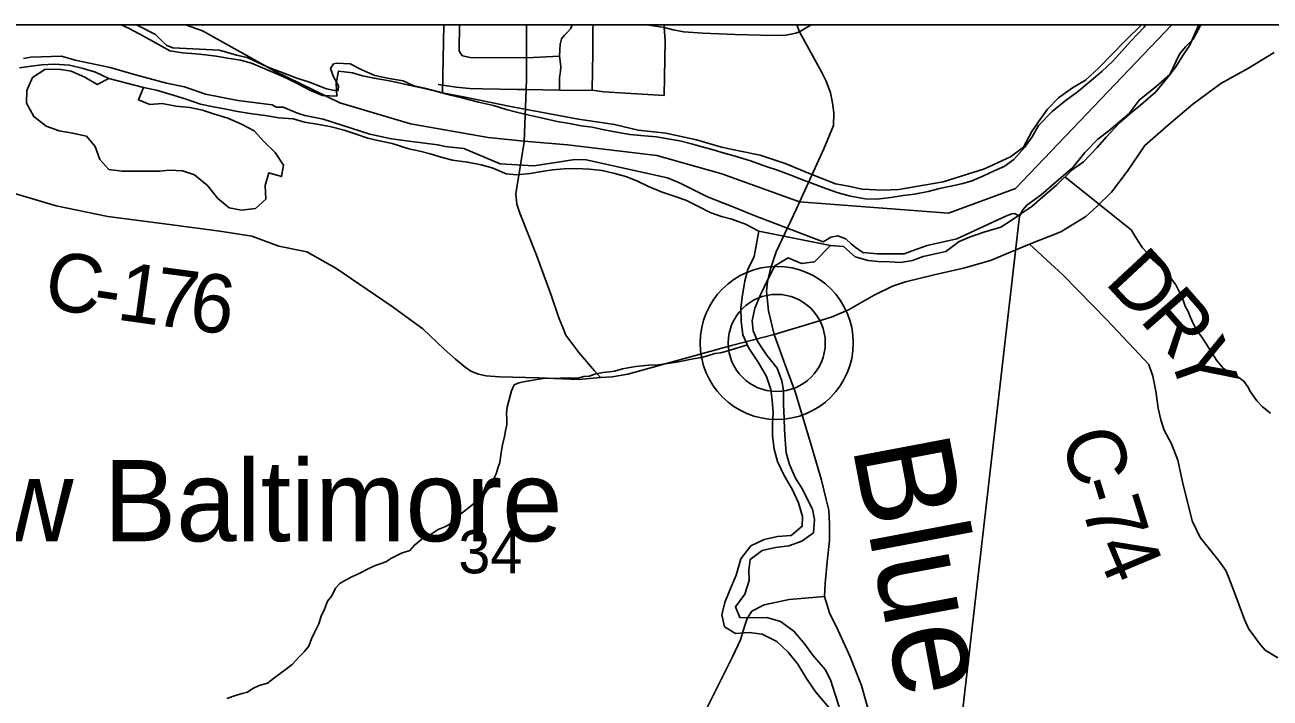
# Model space of a CAD drawing. Extents: x 0 to 34, y 0 to 22.
# Drawn here: x 5.755 to 6.965, y 20.246 to 20.9 of the extents above; entities that cross this region are included whole.
import ezdxf

# ---------------------------------------------------------------- set-up
doc = ezdxf.new("R2010")
doc.units = 0
for name, color, linetype in [('Default', 7, 'Continuous'), ('GM_X_County_Road', 7, 'Continuous'), ('GM_X_County_Road_Text', 7, 'Continuous'), ('GM_X_Major_River', 7, 'Continuous'), ('GM_X_Minor_River', 7, 'Continuous'), ('GM_X_Minor_River_Text', 7, 'Continuous'), ('GM_X_Section', 7, 'Continuous'), ('GM_X_Section_Text', 7, 'Continuous'), ('GM_X_State_Route', 7, 'Continuous'), ('GM_X_Township_Road', 7, 'Continuous'), ('GM_X_Unincorporated', 7, 'Continuous'), ('GM_X_Unincorporated_Location', 7, 'Continuous'), ('GM_X_Unincorporated_Text', 7, 'Continuous'), ('SH_Data', 7, 'Continuous')]:
    doc.layers.add(name, color=color, linetype=linetype)

msp = doc.modelspace()

# ---------------------------------------------------------------- linework, layer by layer
at = {"layer": 'Default'}
for points in [[(6.1618, 20.9), (5.8632, 20.9), (5.8814, 20.8906), (5.888, 20.8843), (5.8925, 20.8801), (5.8985, 20.8777), (5.9439, 20.8754), (5.9604, 20.8705), (5.9706, 20.8683), (5.9901, 20.8591), (6.0021, 20.8547), (6.019, 20.8482), (6.0303, 20.8445), (6.0479, 20.8377), (6.0555, 20.8363), (6.0592, 20.8363), (6.0593, 20.8408), (6.0546, 20.8496), (6.0518, 20.8576), (6.0546, 20.8621), (6.0576, 20.8628), (6.0709, 20.8621), (6.0821, 20.8562), (6.0948, 20.8509), (6.1088, 20.8479), (6.1224, 20.8457), (6.1328, 20.8409), (6.143, 20.8384), (6.1607, 20.8338)], [(6.8402, 20.9), (6.1618, 20.9), (6.1607, 20.8338), (6.1826, 20.8299), (6.2267, 20.8208), (6.2927, 20.8082), (6.3278, 20.8032), (6.3508, 20.7977), (6.3776, 20.7948), (6.4074, 20.7884), (6.4318, 20.781), (6.4503, 20.7772), (6.4695, 20.7733), (6.4936, 20.7651), (6.5179, 20.7551), (6.5427, 20.7454), (6.5552, 20.7432), (6.5687, 20.7402), (6.5888, 20.7393), (6.6043, 20.7401), (6.6473, 20.7474), (6.6874, 20.76), (6.7127, 20.7719), (6.7254, 20.7811), (6.7337, 20.7964), (6.7396, 20.8054), (6.7487, 20.818), (6.7595, 20.8291), (6.773, 20.8387), (6.7857, 20.8463), (6.7985, 20.8581), (6.8245, 20.8848)], [(7.4473, 20.9), (6.898, 20.9), (6.8905, 20.8862), (6.8831, 20.8788), (6.8772, 20.8714), (6.8677, 20.8519), (6.8545, 20.8401), (6.8379, 20.8269), (6.8281, 20.8138), (6.8084, 20.7969), (6.7976, 20.7888), (6.7851, 20.7759), (6.7734, 20.7614), (6.7572, 20.7474), (6.7425, 20.7348), (6.7286, 20.7246), (6.7247, 20.7201), (6.7215, 20.7141), (6.6475, 20.0689), (7.4124, 20.0219)]]:
    msp.add_lwpolyline(points, close=True, dxfattribs=at)
at = {"layer": 'GM_X_County_Road'}
for p, q in [((6.5051, 20.9), (6.5076, 20.8933)), ((6.5076, 20.8933), (6.5191, 20.9))]:
    msp.add_line(p, q, dxfattribs=at)
for points in [[(6.2421, 20.8476), (6.2423, 20.8681), (6.2422, 20.9)], [(6.3593, 20.9), (6.376, 20.8975), (6.3847, 20.8952), (6.3952, 20.8932), (6.4138, 20.8919), (6.445, 20.8906), (6.482, 20.8898), (6.4945, 20.8899), (6.5042, 20.8921), (6.5076, 20.8933)], [(6.5076, 20.8933), (6.5295, 20.8536), (6.5335, 20.8453), (6.5378, 20.834), (6.5397, 20.8242), (6.5411, 20.8145), (6.5406, 20.8022), (6.5313, 20.7796), (6.5077, 20.7276), (6.5048, 20.7213)], [(6.483, 20.5991), (6.5239, 20.6114), (6.5394, 20.6162), (6.5552, 20.6229), (6.5802, 20.6371), (6.5982, 20.6461), (6.6106, 20.6501), (6.6385, 20.657), (6.667, 20.6634), (6.6933, 20.6708), (6.7314, 20.6867), (6.7616, 20.6989), (6.7859, 20.7138), (6.7968, 20.7233), (6.8109, 20.7374), (6.8263, 20.7575), (6.8434, 20.7828), (6.8667, 20.8031), (6.8901, 20.8229), (6.9172, 20.8431), (6.9443, 20.8579), (6.969, 20.8732)], [(6.2401, 20.7864), (6.242, 20.8373), (6.2421, 20.8476)], [(6.2768, 20.6074), (6.2736, 20.6153), (6.2661, 20.6374), (6.2518, 20.6763), (6.2358, 20.717), (6.2327, 20.7256), (6.232, 20.7359), (6.2401, 20.7864)], [(5.7288, 20.7406), (5.785, 20.7242), (5.8352, 20.7136), (5.895, 20.7059), (5.9442, 20.6995), (5.9752, 20.6945), (6.0015, 20.685), (6.0287, 20.6793), (6.0569, 20.6634), (6.1106, 20.627), (6.1415, 20.6045), (6.1622, 20.5846), (6.1731, 20.5749), (6.1826, 20.5672), (6.1881, 20.5633), (6.1956, 20.5605), (6.203, 20.5588), (6.216, 20.5577), (6.2538, 20.5568), (6.2928, 20.5554), (6.3142, 20.5572)], [(6.5048, 20.7213), (6.4851, 20.6794), (6.4796, 20.6627), (6.4764, 20.6503), (6.4756, 20.6413), (6.4775, 20.6219), (6.483, 20.5991)], [(6.7314, 20.6867), (6.7638, 20.657), (6.8065, 20.6133), (6.8329, 20.5852), (6.8472, 20.5698), (6.8511, 20.5585), (6.8542, 20.544), (6.8565, 20.5275), (6.859, 20.5162), (6.8623, 20.506), (6.8692, 20.4928), (6.8756, 20.4768), (6.8808, 20.4529), (6.8841, 20.4389), (6.8893, 20.418), (6.8973, 20.4016), (6.9067, 20.3901), (6.9156, 20.3785), (6.922, 20.3695), (6.925, 20.3625), (6.9299, 20.3497), (6.9402, 20.3219), (6.9445, 20.3127), (6.9497, 20.3057), (6.9546, 20.2989), (6.9603, 20.292), (6.9727, 20.2847)], [(6.3142, 20.5572), (6.3083, 20.5636), (6.293, 20.5814), (6.2805, 20.5985), (6.2768, 20.6074)], [(6.3142, 20.5572), (6.3255, 20.5578), (6.3406, 20.5603), (6.4416, 20.5884), (6.483, 20.5991)], [(6.483, 20.5991), (6.4951, 20.5661), (6.5033, 20.5433), (6.5176, 20.4961), (6.5292, 20.4573), (6.5335, 20.4387), (6.5361, 20.4282), (6.5369, 20.4149), (6.5367, 20.3986), (6.5344, 20.3779), (6.5325, 20.3569), (6.5319, 20.3443), (6.5369, 20.3283), (6.5453, 20.3111), (6.5569, 20.2857), (6.5678, 20.2579), (6.5768, 20.2264)], [(6.4543, 20.315), (6.4569, 20.3229), (6.4612, 20.33), (6.4732, 20.3361), (6.4977, 20.3413), (6.5319, 20.3443)], [(6.4159, 20.2324), (6.4425, 20.2857), (6.4502, 20.3022), (6.4543, 20.315)]]:
    msp.add_lwpolyline(points, dxfattribs=at)
at = {"layer": 'GM_X_Major_River'}
for p, q in [((5.8363, 20.848), (5.8699, 20.8392)), ((6.4682, 20.6995), (6.5378, 20.6854))]:
    msp.add_line(p, q, dxfattribs=at)
for points in [[(6.8441, 20.9), (6.8426, 20.8979), (6.8301, 20.8845), (6.8211, 20.8744), (6.8122, 20.8647), (6.8017, 20.8547), (6.7916, 20.8462), (6.7793, 20.8358), (6.7657, 20.8259), (6.7534, 20.8159), (6.7401, 20.8021), (6.7338, 20.7912), (6.7264, 20.7807), (6.7162, 20.7692), (6.7066, 20.7622), (6.697, 20.7582), (6.6859, 20.7528), (6.6747, 20.7481), (6.6652, 20.7456), (6.6549, 20.7432), (6.6438, 20.7408), (6.6327, 20.738), (6.6194, 20.7356), (6.6083, 20.734), (6.5965, 20.7323), (6.5828, 20.7307), (6.5714, 20.731), (6.5571, 20.7336), (6.5454, 20.7369), (6.5333, 20.741), (6.5228, 20.745), (6.5115, 20.7491), (6.4991, 20.7539), (6.4863, 20.7588), (6.4753, 20.7625), (6.4599, 20.7677), (6.4452, 20.7723), (6.4335, 20.7756), (6.4237, 20.7785), (6.4131, 20.7814), (6.4014, 20.7847), (6.3912, 20.7872), (6.3795, 20.7893), (6.3685, 20.7911), (6.3571, 20.7921), (6.3427, 20.7936), (6.3299, 20.7958), (6.3178, 20.798), (6.3061, 20.8005), (6.2955, 20.8019), (6.2841, 20.804), (6.272, 20.8062), (6.2565, 20.8096), (6.2448, 20.8121), (6.2324, 20.8151), (6.2225, 20.8176), (6.2101, 20.8217), (6.1957, 20.825), (6.1795, 20.8292), (6.1682, 20.8317), (6.1538, 20.8355), (6.1402, 20.8388), (6.1278, 20.8414), (6.1168, 20.8439), (6.107, 20.8461), (6.0941, 20.8482), (6.0828, 20.8504), (6.073, 20.8533), (6.0593, 20.8551), (6.0572, 20.8434), (6.0577, 20.8308), (6.044, 20.8315), (6.0316, 20.8367), (6.0207, 20.8423), (6.0094, 20.8479), (5.9985, 20.8527), (5.9857, 20.8583), (5.9748, 20.8627), (5.9643, 20.8656), (5.9514, 20.8678), (5.9404, 20.8696), (5.9302, 20.8709), (5.9207, 20.8719), (5.9079, 20.873), (5.8954, 20.8748), (5.8822, 20.8823), (5.8699, 20.889), (5.856, 20.8966), (5.8482, 20.9)], [(6.5378, 20.6854), (6.5506, 20.6847), (6.5618, 20.6746), (6.5743, 20.6709), (6.5841, 20.6699), (6.5955, 20.6696), (6.6057, 20.669), (6.6175, 20.671), (6.6279, 20.675), (6.6382, 20.677), (6.65, 20.6798), (6.6628, 20.6894), (6.6731, 20.6937), (6.6869, 20.6984), (6.7033, 20.7033), (6.7134, 20.7099), (6.7238, 20.7169), (6.7334, 20.7235), (6.7443, 20.7328), (6.7574, 20.7443), (6.7726, 20.7592), (6.7838, 20.7669), (6.797, 20.7807), (6.8059, 20.7907), (6.8188, 20.8049), (6.8289, 20.8134), (6.8393, 20.8219), (6.854, 20.8349), (6.8657, 20.8491), (6.8736, 20.8592), (6.8803, 20.8704), (6.887, 20.8802), (6.8926, 20.893), (6.896, 20.9)], [(5.7492, 20.8583), (5.7606, 20.8599), (5.7709, 20.8612), (5.7834, 20.8617), (5.7978, 20.861), (5.8111, 20.8577), (5.8231, 20.854), (5.8363, 20.848)], [(5.8699, 20.8392), (5.8824, 20.8367), (5.8955, 20.8326), (5.9103, 20.828), (5.9253, 20.8231), (5.9378, 20.8202), (5.9503, 20.818), (5.9612, 20.8159), (5.9756, 20.8136), (5.9881, 20.8118), (6.0014, 20.8096), (6.0154, 20.8086), (6.0263, 20.8053), (6.0384, 20.8035), (6.0509, 20.8013), (6.0649, 20.7976), (6.0747, 20.7943), (6.0879, 20.7898), (6.0977, 20.7877), (6.1117, 20.7847), (6.1279, 20.7794), (6.1385, 20.7773), (6.1487, 20.7748), (6.1592, 20.7715), (6.1702, 20.7686), (6.1849, 20.7667), (6.1982, 20.7641), (6.2087, 20.7612), (6.2226, 20.7552), (6.2325, 20.7542), (6.2458, 20.7555), (6.2572, 20.7575), (6.2675, 20.7592), (6.2789, 20.76), (6.2907, 20.7605), (6.3036, 20.7599), (6.3157, 20.7585), (6.3282, 20.7555), (6.3399, 20.7522), (6.3501, 20.7482), (6.361, 20.743), (6.3741, 20.7374), (6.3869, 20.7333), (6.3971, 20.7296), (6.4095, 20.7236), (6.4208, 20.7177), (6.4317, 20.7136), (6.4419, 20.7111), (6.4551, 20.7063), (6.4682, 20.6995)]]:
    msp.add_lwpolyline(points, dxfattribs=at)
at = {"layer": 'GM_X_Minor_River'}
for p, q in [((5.8699, 20.8392), (5.8363, 20.848)), ((6.5378, 20.6854), (6.4682, 20.6995))]:
    msp.add_line(p, q, dxfattribs=at)
for points in [[(5.8363, 20.848), (5.8248, 20.8421), (5.8128, 20.8492), (5.7996, 20.8549), (5.7875, 20.857), (5.7738, 20.8566), (5.7619, 20.8489), (5.7563, 20.8361), (5.756, 20.8239), (5.7633, 20.8108), (5.7752, 20.8014), (5.788, 20.7969), (5.8009, 20.7948), (5.8145, 20.7918), (5.823, 20.7817), (5.8273, 20.7691), (5.8362, 20.7594), (5.8491, 20.7579), (5.8616, 20.7577), (5.876, 20.7577), (5.8855, 20.7579), (5.895, 20.7588), (5.9079, 20.7581), (5.9196, 20.7541), (5.9323, 20.7435), (5.9419, 20.7315), (5.953, 20.7221), (5.9651, 20.72), (5.9789, 20.7216), (5.9889, 20.7305), (5.9881, 20.7438), (5.9918, 20.7562), (6.0042, 20.7525), (6.006, 20.7635), (5.9979, 20.7759), (5.9872, 20.7864), (5.9775, 20.7969), (5.9651, 20.8036), (5.952, 20.8092), (5.938, 20.8137), (5.9271, 20.817), (5.915, 20.8196), (5.9014, 20.821), (5.8881, 20.8236), (5.876, 20.8227), (5.865, 20.8272), (5.8699, 20.8392)], [(6.7655, 20.7523), (6.8302, 20.7007), (6.8336, 20.6949), (6.8369, 20.6899), (6.8413, 20.6833), (6.8462, 20.6776), (6.8507, 20.6722), (6.8611, 20.6628), (6.8664, 20.657), (6.8697, 20.6524), (6.8734, 20.6474), (6.8764, 20.6416), (6.8793, 20.6363), (6.8826, 20.6267), (6.8855, 20.6213), (6.8877, 20.6155), (6.891, 20.6083), (6.8947, 20.6021), (6.8988, 20.5963), (6.9021, 20.5917), (6.9054, 20.5863), (6.9099, 20.5794), (6.9132, 20.574), (6.9195, 20.5663), (6.9274, 20.5608), (6.9338, 20.5577), (6.9395, 20.5538), (6.9436, 20.548), (6.9461, 20.5434), (6.9524, 20.5345), (6.9577, 20.5287), (6.9656, 20.5225)], [(6.4682, 20.6995), (6.4635, 20.6749), (6.4575, 20.6621), (6.4546, 20.6511), (6.4519, 20.6352), (6.4506, 20.6246), (6.451, 20.612), (6.4526, 20.5987), (6.4584, 20.5856), (6.4676, 20.5721), (6.4756, 20.5583), (6.4799, 20.5456), (6.4812, 20.5353), (6.482, 20.5227), (6.4814, 20.5129), (6.4815, 20.5007), (6.4831, 20.4874), (6.4863, 20.4755), (6.4928, 20.462), (6.5005, 20.4486), (6.5067, 20.4355), (6.5105, 20.4221), (6.5103, 20.4126), (6.4995, 20.4037), (6.4862, 20.4025), (6.4732, 20.3997), (6.4605, 20.3936), (6.4507, 20.3809), (6.4462, 20.365), (6.4406, 20.3522), (6.435, 20.3386), (6.432, 20.3265), (6.4348, 20.3147), (6.4453, 20.3084), (6.4586, 20.3092), (6.4715, 20.3078), (6.4857, 20.3006), (6.4965, 20.2901), (6.5061, 20.2785), (6.5145, 20.2646), (6.5237, 20.2514), (6.5474, 20.2232)], [(6.5462, 20.2369), (6.5423, 20.2491), (6.5377, 20.2633), (6.5326, 20.2733), (6.5204, 20.2876), (6.5127, 20.2981), (6.5023, 20.3105), (6.4892, 20.3199), (6.476, 20.324), (6.4627, 20.3236), (6.4498, 20.3238), (6.4455, 20.3342), (6.4545, 20.3466), (6.4586, 20.3598), (6.4585, 20.37), (6.4598, 20.3803), (6.4714, 20.3891), (6.4844, 20.3919), (6.4973, 20.3935), (6.51, 20.3982), (6.5212, 20.4063), (6.5222, 20.4192), (6.5202, 20.4291), (6.5155, 20.4387), (6.5107, 20.4487), (6.5038, 20.4595), (6.498, 20.4726), (6.4948, 20.4841), (6.4936, 20.4966), (6.4931, 20.5065), (6.4926, 20.5172), (6.4921, 20.5309), (6.492, 20.5446), (6.4904, 20.5541), (6.4861, 20.5664), (6.4757, 20.5792), (6.4673, 20.5919), (6.4626, 20.6027), (6.4617, 20.6122), (6.4642, 20.6247), (6.4698, 20.6375), (6.477, 20.6525), (6.4838, 20.6657), (6.4965, 20.6734), (6.5096, 20.6681), (6.5222, 20.6698), (6.5378, 20.6854)], [(6.457, 20.5889), (6.4371, 20.5829), (6.431, 20.5811), (6.4253, 20.5804), (6.4172, 20.5779), (6.4123, 20.5768), (6.4043, 20.5754), (6.3901, 20.5726), (6.3794, 20.5709), (6.3703, 20.5695), (6.3611, 20.5693), (6.3546, 20.5686), (6.3485, 20.5679), (6.3428, 20.5669), (6.3356, 20.5655), (6.3279, 20.5633), (6.3229, 20.5626), (6.3165, 20.562), (6.3096, 20.5609), (6.3031, 20.5584), (6.2981, 20.5581), (6.2931, 20.557), (6.2886, 20.5567), (6.2836, 20.5568), (6.2749, 20.5566), (6.2688, 20.5563), (6.2638, 20.5564), (6.2585, 20.5561), (6.2524, 20.5554), (6.2447, 20.554), (6.2394, 20.5529), (6.2348, 20.5519), (6.2302, 20.55), (6.2278, 20.5444), (6.225, 20.5345), (6.2233, 20.5284), (6.2228, 20.5224), (6.2231, 20.5159), (6.223, 20.5113), (6.2218, 20.5052), (6.2209, 20.4999), (6.2189, 20.4919), (6.2176, 20.4843), (6.2163, 20.4745), (6.2143, 20.4692), (6.2126, 20.4635), (6.2095, 20.457), (6.2063, 20.451), (6.202, 20.4446), (6.1962, 20.439), (6.1892, 20.433), (6.1838, 20.4289), (6.1769, 20.4233), (6.1722, 20.4177), (6.1676, 20.4147), (6.163, 20.4121), (6.1565, 20.4095), (6.1476, 20.4036), (6.1422, 20.4014), (6.1333, 20.3943), (6.1287, 20.389), (6.1206, 20.3865), (6.111, 20.3817), (6.1056, 20.378), (6.101, 20.3765), (6.0961, 20.3747), (6.0903, 20.3721), (6.0788, 20.3662), (6.073, 20.3636), (6.0661, 20.3603), (6.0607, 20.357), (6.0564, 20.3525), (6.0529, 20.3449), (6.0486, 20.3397), (6.0458, 20.3321), (6.0426, 20.3253), (6.0402, 20.3177), (6.0366, 20.3098), (6.0331, 20.303), (6.0307, 20.2961), (6.026, 20.2905), (6.0213, 20.2856), (6.0144, 20.2781), (6.009, 20.274), (6.0016, 20.2684), (5.9962, 20.2647), (5.9904, 20.2602), (5.9824, 20.2577), (5.9762, 20.2547), (5.9709, 20.2514), (5.9659, 20.25), (5.9594, 20.2482), (5.9509, 20.2452)]]:
    msp.add_lwpolyline(points, dxfattribs=at)
at = {"layer": 'GM_X_Section'}
msp.add_lwpolyline([(5.7531, 20.8675), (5.7604, 20.8685), (5.7903, 20.8697), (5.8035, 20.8656), (5.8374, 20.8587), (5.8622, 20.8516), (5.8923, 20.8433), (5.9097, 20.8399), (5.9303, 20.8326), (5.9616, 20.8265), (5.9949, 20.8223), (5.999, 20.8199), (6.0058, 20.8201), (6.0197, 20.8141), (6.0268, 20.812), (6.0445, 20.8082), (6.09, 20.7938), (6.1111, 20.7892), (6.133, 20.7864), (6.1561, 20.7835), (6.1632, 20.7818), (6.1814, 20.7799), (6.2166, 20.765), (6.2495, 20.7631), (6.2686, 20.766), (6.2891, 20.7693), (6.3001, 20.7687), (6.3426, 20.7593), (6.3792, 20.7512), (6.3916, 20.746), (6.4181, 20.7329), (6.4437, 20.7228), (6.4635, 20.7147), (6.5307, 20.6892), (6.5346, 20.6914), (6.538, 20.6936), (6.5449, 20.6949), (6.5528, 20.6921), (6.558, 20.687), (6.5617, 20.6839), (6.5691, 20.6788), (6.5835, 20.6773), (6.6093, 20.6775), (6.6173, 20.6803), (6.6318, 20.6856), (6.6607, 20.6921), (6.709, 20.7144), (6.714, 20.7162), (6.7167, 20.7165), (6.7215, 20.7141), (6.6475, 20.0689)], dxfattribs=at)
at = {"layer": 'GM_X_State_Route'}
msp.add_lwpolyline([(8.9, 16.8616), (8.9, 20.9), (6.8697, 20.9), (6.7177, 20.7411), (6.6525, 20.7169), (6.5075, 20.7281), (6.4321, 20.7553), (6.3691, 20.7729), (6.282, 20.7835), (6.2399, 20.787), (6.2051, 20.7905), (6.1295, 20.8038), (6.0609, 20.8242), (5.9975, 20.8551), (5.9272, 20.8941), (5.9107, 20.9), (5.6847, 20.9)], dxfattribs=at)
msp.add_lwpolyline([(6.8697, 20.9), (5.9107, 20.9), (5.9272, 20.8941), (5.9975, 20.8551), (6.0609, 20.8242), (6.1295, 20.8038), (6.2051, 20.7905), (6.2399, 20.787), (6.282, 20.7835), (6.3691, 20.7729), (6.4321, 20.7553), (6.5075, 20.7281), (6.6525, 20.7169), (6.7177, 20.7411)], close=True, dxfattribs=at)
at = {"layer": 'GM_X_Township_Road'}
msp.add_line((6.1772, 20.9), (6.1767, 20.8751), dxfattribs=at)
for points in [[(6.2744, 20.8367), (6.2743, 20.8488), (6.2752, 20.8547), (6.2757, 20.8595), (6.2742, 20.8695), (6.2749, 20.8812), (6.2762, 20.8866), (6.2791, 20.8901), (6.2819, 20.8927), (6.2854, 20.8965), (6.2865, 20.9)], [(6.3072, 20.9), (6.3068, 20.8963), (6.3066, 20.8732), (6.3061, 20.8365)], [(6.3761, 20.9), (6.376, 20.8975), (6.3771, 20.8848), (6.376, 20.8314)], [(6.1767, 20.8751), (6.178, 20.8723), (6.18, 20.87), (6.1874, 20.8684), (6.2423, 20.8681), (6.2742, 20.8695)], [(6.1993, 20.8379), (6.1867, 20.8381), (6.1739, 20.8395), (6.1565, 20.8421)], [(6.242, 20.8373), (6.2329, 20.8373), (6.1993, 20.8379)], [(6.376, 20.8314), (6.3174, 20.8348), (6.3061, 20.8365), (6.2951, 20.8363), (6.2744, 20.8367), (6.242, 20.8373)]]:
    msp.add_lwpolyline(points, dxfattribs=at)
at = {"layer": 'GM_X_Unincorporated'}
for radius in [0.0744, 0.0472]:
    msp.add_circle((6.4855, 20.5908), radius, dxfattribs=at)
at = {"layer": 'GM_X_Unincorporated_Location'}
msp.add_line((6.4855, 20.5908), (6.4855, 20.5908), dxfattribs=at)
at = {"layer": 'SH_Data'}
msp.add_line((2.1, 20.9), (8.9, 20.9), dxfattribs=at)

# ---------------------------------------------------------------- texts
at = {"layer": 'GM_X_County_Road_Text'}
for s, rotation, p in [('C', 349.3103, (5.7708, 20.6263)), ('D', 312.964, (6.8034, 20.6493)), ('1', 351.9682, (5.8426, 20.6137)), ('7', 352.3966, (5.8777, 20.6087)), ('6', 352.5029, (5.9125, 20.6041)), ('-', 351.4236, (5.819, 20.6173)), ('R', 311.2392, (6.8372, 20.6131)), ('Y', 289.7451, (6.8651, 20.5828)), ('C', 285.9525, (6.7616, 20.5)), ('-', 286.9817, (6.7748, 20.454)), ('7', 287.2144, (6.7816, 20.4315)), ('4', 292.7904, (6.7941, 20.3924))]:
    msp.add_text(s, height=0.0568, rotation=rotation, dxfattribs=at).set_placement(p)
at = {"layer": 'GM_X_Minor_River_Text'}
msp.add_text('Blue', height=0.0947, rotation=280.7184, dxfattribs=at).set_placement((6.5587, 20.4907))
at = {"layer": 'GM_X_Section_Text'}
msp.add_text('34', height=0.04186, rotation=0, dxfattribs=at).set_placement((6.176, 20.3668))
at = {"layer": 'GM_X_Unincorporated_Text'}
msp.add_text('New Baltimore', height=0.078977, rotation=0, dxfattribs=at).set_placement((5.5906, 20.398))

doc.saveas('drawing.dxf')
